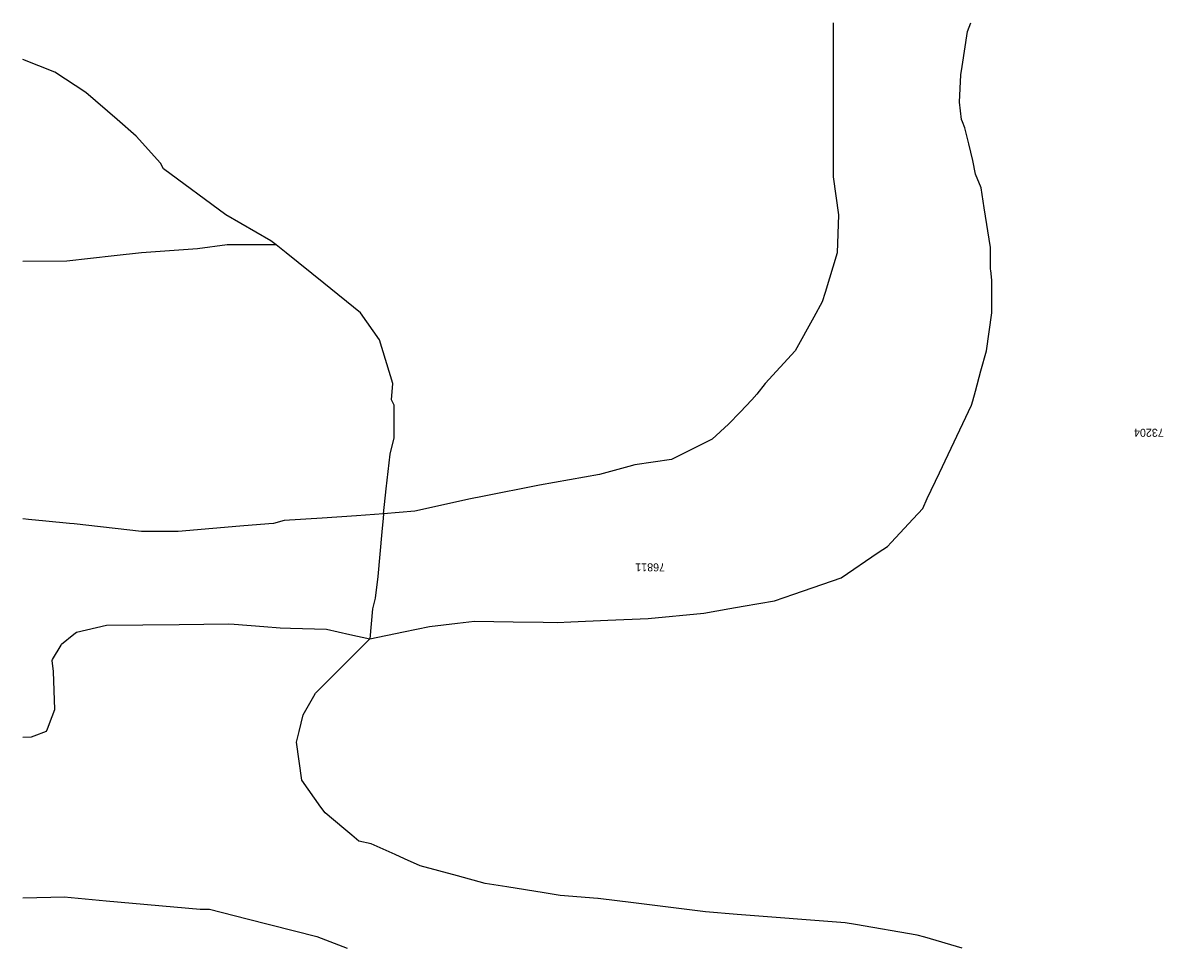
# Model space of a CAD drawing. Extents: x -778045 to -768365, y -1202571 to -1202059.
# Drawn here: x -768721 to -768364.7, y -1202348.4 to -1202059.4 of the extents above; entities that cross this region are included whole.
import ezdxf

# ---------------------------------------------------------------- set-up
doc = ezdxf.new("R2010")
doc.units = 0
doc.layers.add('BPEJ', color=7, linetype='Continuous')

msp = doc.modelspace()

# ---------------------------------------------------------------- linework, layer by layer
at = {"layer": 'BPEJ'}
for points in [[(-768467.87, -1202059.44), (-768467.87, -1202060.03), (-768467.87, -1202066.82), (-768467.87, -1202068.96), (-768467.87, -1202089.62), (-768467.87, -1202102.46), (-768467.87, -1202106.12), (-768467.87, -1202107.56), (-768466.17, -1202119.44), (-768466.38, -1202125.34), (-768466.6, -1202131.32), (-768470.37, -1202143.66), (-768471.25, -1202146.55), (-768471.27, -1202146.59), (-768473.9, -1202151.34), (-768479.75, -1202161.87), (-768484.42, -1202166.96), (-768489.09, -1202172.05), (-768491.63, -1202175.45), (-768493.26, -1202177.15), (-768496.92, -1202180.99), (-768500.54, -1202184.78), (-768505.64, -1202189.45), (-768518.37, -1202195.82), (-768529.82, -1202197.51), (-768531.7, -1202198.02), (-768540.85, -1202200.48), (-768559.52, -1202203.88), (-768577.35, -1202207.37), (-768581.16, -1202208.12), (-768598.56, -1202211.94), (-768608.32, -1202212.79)], [(-768585.22, -1202246.96), (-768579.89, -1202246.31), (-768567.76, -1202246.51), (-768558.42, -1202246.66), (-768554.01, -1202246.73), (-768549.83, -1202246.55), (-768538.18, -1202246.03), (-768525.58, -1202245.46), (-768508.18, -1202243.76), (-768500.1, -1202242.36), (-768495.91, -1202241.64), (-768486.12, -1202239.95), (-768480.07, -1202237.85), (-768465.32, -1202232.73), (-768453.72, -1202224.88), (-768450.9, -1202222.97), (-768449.71, -1202221.69), (-768442.87, -1202214.32), (-768439.87, -1202211.09), (-768438.43, -1202208.05), (-768434.62, -1202200.02), (-768424.59, -1202178.84), (-768424.22, -1202177.49), (-768423.4, -1202174.52), (-768421.65, -1202168.16), (-768419.92, -1202161.87), (-768418.23, -1202149.99), (-768418.23, -1202139.8), (-768418.6, -1202136.8), (-768418.65, -1202136.41), (-768418.65, -1202129.62), (-768420.62, -1202117.23), (-768421.62, -1202110.95), (-768423.32, -1202106.71), (-768424.17, -1202102.46), (-768425.47, -1202097.25), (-768426.71, -1202092.28), (-768427.42, -1202090.41), (-768427.71, -1202089.62), (-768428.41, -1202084.22), (-768427.98, -1202075.73), (-768427.57, -1202073.05), (-768425.86, -1202062.15), (-768424.81, -1202059.44)], [(-768641.84, -1202128.77), (-768643.54, -1202127.5), (-768657.54, -1202119.44), (-768677.06, -1202105.01), (-768677.91, -1202103.31), (-768685.55, -1202094.83), (-768691.49, -1202089.62), (-768701.25, -1202081.25), (-768711.01, -1202074.88), (-768720.97, -1202070.94)], [(-768641.84, -1202128.77), (-768657.12, -1202128.77), (-768666.45, -1202130.05), (-768683.85, -1202131.32), (-768692.45, -1202132.26), (-768707.19, -1202133.87), (-768720.97, -1202134.01)], [(-768608.32, -1202212.79), (-768607.43, -1202204.98), (-768606.2, -1202194.12), (-768604.93, -1202189.03), (-768604.93, -1202186.17), (-768604.93, -1202178.84), (-768605.78, -1202177.14), (-768605.35, -1202172.05), (-768609.59, -1202158.48), (-768615.53, -1202149.99), (-768626.96, -1202140.78), (-768638.71, -1202131.3), (-768641.84, -1202128.77)], [(-768608.32, -1202212.79), (-768616.75, -1202213.37), (-768627.41, -1202214.1), (-768639.3, -1202214.91), (-768642.69, -1202215.76), (-768644.13, -1202215.88), (-768653.17, -1202216.66), (-768661.59, -1202217.38), (-768672.39, -1202218.3), (-768683.85, -1202218.3), (-768704.9, -1202215.92), (-768706.34, -1202215.76), (-768713.74, -1202215.06), (-768719.21, -1202214.55), (-768720.97, -1202214.38)], [(-768608.32, -1202212.79), (-768608.44, -1202214.12), (-768608.81, -1202218.42), (-768610.02, -1202232.31), (-768610.87, -1202239.1), (-768611.72, -1202242.49), (-768612.56, -1202251.83)], [(-768713.55, -1202280.68), (-768713.25, -1202279.89), (-768711.81, -1202276.04), (-768711.01, -1202273.89), (-768711.43, -1202262.01), (-768711.85, -1202258.61), (-768711.66, -1202258.28), (-768709.04, -1202253.8), (-768708.88, -1202253.52), (-768705.08, -1202250.41), (-768704.22, -1202249.7), (-768694.88, -1202247.58), (-768672.12, -1202247.33), (-768656.69, -1202247.16), (-768654.98, -1202247.29), (-768645.73, -1202248.02), (-768640.57, -1202248.43), (-768637.3, -1202248.53), (-768626.14, -1202248.85), (-768618.84, -1202250.45), (-768612.56, -1202251.83)], [(-768612.56, -1202251.83), (-768602.01, -1202249.67), (-768593.89, -1202248.01), (-768585.22, -1202246.96)], [(-768427.52, -1202348.44), (-768439.24, -1202345.01), (-768441.56, -1202344.33), (-768460.84, -1202341.05), (-768464.05, -1202340.51), (-768497.85, -1202337.88), (-768507.76, -1202337.11), (-768530.17, -1202334.28), (-768541.28, -1202332.87), (-768541.31, -1202332.87), (-768553.16, -1202332.02), (-768558.15, -1202331.2), (-768569.73, -1202329.31), (-768576.5, -1202328.2), (-768585.23, -1202325.84), (-768596.86, -1202322.69), (-768601.72, -1202320.53), (-768604.64, -1202319.23), (-768612.14, -1202315.9), (-768615.96, -1202315.05), (-768618.17, -1202313.19), (-768620.7, -1202311.07), (-768626.57, -1202306.14), (-768627.83, -1202304.36), (-768633.78, -1202295.95), (-768635.48, -1202284.07), (-768634.66, -1202280.81), (-768633.36, -1202275.59), (-768630.05, -1202269.72), (-768629.54, -1202268.8), (-768619.35, -1202258.61), (-768617.58, -1202256.84), (-768612.56, -1202251.83)], [(-768720.97, -1202282.57), (-768718.22, -1202282.38), (-768717.41, -1202282.08), (-768713.55, -1202280.68)], [(-768720.97, -1202332.68), (-768712.23, -1202332.52), (-768708.04, -1202332.45), (-768694.95, -1202333.62), (-768665.6, -1202336.26), (-768662.63, -1202336.26), (-768650.92, -1202339.23), (-768629.11, -1202344.75), (-768619.65, -1202348.44)]]:
    msp.add_lwpolyline(points, dxfattribs=at)

# ---------------------------------------------------------------- texts
for s, p in [('73204', (-768364.56, -1202186.23)), ('76811', (-768520.35, -1202228.26))]:
    msp.add_text(s, height=2.5, rotation=180, dxfattribs=at).set_placement(p)

doc.saveas('drawing.dxf')
